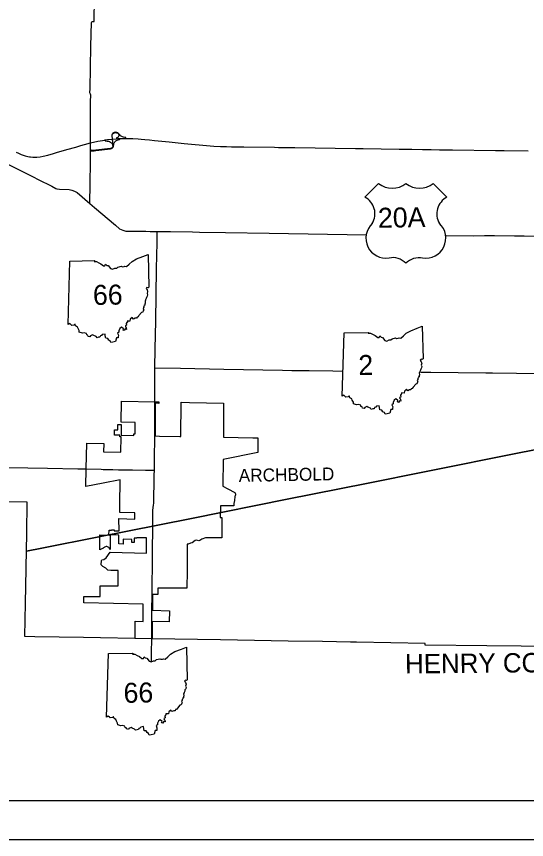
# Model space of a CAD drawing. Extents: x 0 to 849, y 0 to 440.
# Drawn here: x 135.7 to 267.5, y 0 to 212.6 of the extents above; entities that cross this region are included whole.
import ezdxf

# ---------------------------------------------------------------- set-up
doc = ezdxf.new("R2010")
doc.units = 0
for name, color, linetype in [('DV_X_Corp_Line', 7, 'Continuous'), ('GM_X_Adjacent_County_Text', 7, 'Continuous'), ('GM_X_Corporation_Text', 7, 'Continuous'), ('GM_X_County', 7, 'Continuous'), ('GM_X_Interchange_Ramps', 7, 'Continuous'), ('GM_X_Interstate_Route', 7, 'Continuous'), ('PV_P_Walk', 7, 'Continuous'), ('RD_X_RR_2', 7, 'Continuous'), ('SH_Border', 7, 'Continuous'), ('SH_Cut_Line', 7, 'Continuous')]:
    doc.layers.add(name, color=color, linetype=linetype)

msp = doc.modelspace()

# ---------------------------------------------------------------- linework, layer by layer
at = {"layer": 'DV_X_Corp_Line'}
msp.add_lwpolyline([(157.2, 77.1), (157.21, 78.66), (159.7, 78.59), (159.56, 78.74), (159.59, 79.89), (160.22, 79.89), (160.24, 79.97), (160.9, 79.99), (160.92, 79.74), (162.19, 79.7), (162.13, 82.88), (166.24, 82.79), (166.24, 84.37), (162.36, 84.48), (162.38, 86.49), (162.46, 92.87), (158.09, 92.04), (153.6, 91.15), (153.7, 95.78), (153.83, 102.38), (158.21, 102.29), (158.18, 100.17), (162.64, 100.09), (162.69, 103.98), (162.35, 103.99), (162.36, 104.42), (160.95, 104.44), (160.96, 105.85), (161.84, 105.85), (161.85, 107.21), (162.7, 107.19), (162.7, 104.41), (166.02, 104.34), (166.03, 104.79), (166.37, 104.79), (166.37, 107.72), (162.73, 107.8), (162.76, 113.26), (171.53, 113.08), (172.43, 113.07), (172.43, 112.65), (171.53, 112.67), (171.54, 112.32), (171.54, 110.86), (171.53, 108.11), (171.53, 105.38), (171.53, 104.24), (172.65, 104.21), (177.9, 104.11), (178.16, 104.11), (178.21, 112.95), (180.39, 112.91), (189.2, 112.74), (189.2, 103.9), (196.77, 103.79), (198.02, 103.78), (198.01, 99.99), (189.11, 98.19), (189.1, 98.04), (188.97, 91.57), (188.96, 91.24), (190.26, 90.57), (192.07, 89.64), (192.21, 89.46), (192.29, 89.22), (192.26, 89.03), (192.21, 88.8), (192.05, 88.6), (191.97, 87.56), (191.87, 86.79), (191.83, 86.19), (188.85, 86.23), (188.35, 86.23), (188.32, 83.16), (188.77, 83.16), (188.71, 77.9), (184.47, 77.9), (183.59, 77.54), (183.02, 77.21), (182.8, 77.17), (182.14, 77.33), (181.83, 77.22), (181.04, 76.66), (180.65, 76.55), (180.06, 76.29), (179.76, 76.27), (179.74, 69.37), (179.67, 64.92), (172.2, 64.92), (172.2, 63.28), (170.84, 63.28), (170.84, 61.36), (170.84, 59.21), (175.17, 59.11), (175.13, 56.21), (170.75, 56.3), (170.72, 51.85), (166.32, 51.95), (166.31, 53.93), (166.31, 56.38), (168.37, 56.34), (168.37, 60.78), (153.08, 61.15), (153.1, 62.8), (157.26, 62.74), (157.26, 65.51), (161.93, 65.51), (161.92, 69.45), (160.03, 69.46), (159.26, 69.58), (158.73, 70.08), (158, 70.53), (157.54, 70.96), (157.6, 72.11), (157.75, 72.25), (158.2, 72.34), (158.85, 72.76), (159.84, 74.24), (169.23, 74), (169.24, 77.89), (166.77, 77.95), (166.77, 77.85), (166.07, 77.86), (166.07, 76.69), (165.44, 76.69), (165.44, 77.49), (163.27, 77.57), (163.24, 76.31), (162.08, 76.37), (162.07, 78.63), (159.87, 78.69), (159.87, 78.59), (159.86, 74.92), (159.8, 74.96), (159.73, 75.05), (159.67, 75.23), (159.54, 75.41), (159.36, 75.54), (159.18, 75.64), (159, 75.67), (158.82, 75.66), (158.63, 75.61), (158.45, 75.53), (158.3, 75.43), (158.19, 75.35), (158.08, 75.2), (157.9, 75.13), (157.68, 75.07), (157.2, 74.86), (157.19, 75.64)], close=True, dxfattribs=at)
at = {"layer": 'GM_X_County'}
msp.add_lwpolyline([(274.97, 49.87), (257.21, 50.03), (241.23, 50.18), (241.23, 50.62), (223.56, 50.97), (222.01, 51), (214.7, 51.12), (205.85, 51.27), (192.81, 51.48), (188.37, 51.55), (170.6, 51.88), (152.98, 52.21), (140.37, 52.37), (137.82, 52.4), (137.99, 61.06), (138.17, 69.88), (138.17, 70.24), (138.3, 79.03), (138.42, 87.11), (120.76, 87.37)], dxfattribs=at)
at = {"layer": 'GM_X_Interchange_Ramps'}
for points in [[(154.8, 177.89), (154.93, 177.9), (155.75, 177.92), (156.18, 177.94), (159.97, 178.38), (160.2, 178.46), (160.39, 178.58), (160.53, 178.72), (160.63, 178.87), (160.72, 179.09), (160.76, 179.3), (160.79, 179.47), (160.86, 179.75), (160.91, 179.91), (161, 180.05), (161.11, 180.21), (161.2, 180.31), (161.33, 180.43), (161.47, 180.52), (161.65, 180.64), (161.83, 180.71), (161.96, 180.76), (162.1, 180.8), (162.26, 180.84), (162.39, 180.87), (162.37, 181.05)], [(163.94, 181.08), (163.93, 181.34), (163.63, 181.37), (163.31, 181.42), (163.09, 181.49), (162.9, 181.59), (162.69, 181.7), (162.56, 181.79), (162.44, 181.94), (162.28, 182.1), (162.15, 182.26), (161.98, 182.43), (161.83, 182.55), (161.6, 182.62), (161.43, 182.66), (161.26, 182.68), (161.11, 182.66), (160.91, 182.6), (160.72, 182.52), (160.59, 182.42), (160.47, 182.3), (160.4, 182.21), (160.33, 182.06), (160.31, 181.89), (160.42, 180.92), (160.58, 179.63), (160.45, 179.63)], [(160.79, 179.47), (160.68, 179.47), (160.51, 180.93), (160.4, 181.84), (160.42, 182.01), (160.49, 182.16), (160.56, 182.26), (160.68, 182.37), (160.82, 182.47), (161.01, 182.55), (161.21, 182.58), (161.39, 182.58), (161.55, 182.55), (161.69, 182.51), (161.88, 182.41), (162.02, 182.28), (162.14, 182.06), (162.16, 181.95), (162.12, 181.74), (162.05, 181.58), (161.94, 181.44), (161.81, 181.36), (161.68, 181.27), (161.47, 181.21), (161.5, 181)], [(158.56, 180.69), (158.57, 180.5), (159.13, 180.42), (159.4, 180.39), (159.7, 180.27), (159.96, 180.14), (160.13, 179.98), (160.29, 179.83), (160.45, 179.63), (160.51, 179.47), (160.58, 179.19), (160.55, 179.02), (160.46, 178.84), (160.32, 178.67), (160.18, 178.55), (159.98, 178.48), (156.15, 178.03), (155.73, 178.01), (154.93, 178.02), (154.8, 178.03)]]:
    msp.add_lwpolyline(points, dxfattribs=at)
at = {"layer": 'GM_X_Interstate_Route'}
msp.add_line((217.4, 121.04), (220.03, 121), dxfattribs=at)
for points in [[(154.66, 192.87), (154.66, 192.98), (154.68, 193.88), (154.9, 204.94), (155.08, 211.05), (155.13, 211.21), (155.24, 211.26), (155.71, 211.25), (155.78, 211.33), (155.76, 212.2), (155.8, 216.41), (155.83, 218.75), (155.85, 221.05)], [(154.83, 191.03), (154.84, 191.86), (154.84, 192.29), (154.8, 192.52), (154.66, 192.87)], [(154.82, 186.76), (154.82, 187.12), (154.82, 187.48), (154.83, 191.03)], [(154.8, 179.94), (154.8, 182.13), (154.82, 186.76)], [(157.87, 180.57), (158.38, 180.66), (158.56, 180.69), (159.18, 180.77), (160.42, 180.92), (160.51, 180.93), (161.5, 181), (161.96, 181.04), (162.37, 181.05), (163.28, 181.08), (163.94, 181.08), (165.77, 181.07), (167.12, 180.98), (167.88, 180.93), (168.87, 180.83), (170.02, 180.71), (171.37, 180.58), (172.27, 180.49)], [(135.62, 177.53), (136.17, 177.25), (136.57, 177.07), (136.9, 176.93), (137.38, 176.75), (137.93, 176.57), (138.59, 176.42), (138.99, 176.34), (139.32, 176.3), (139.9, 176.25), (140.45, 176.24), (140.95, 176.25), (141.75, 176.32), (142.6, 176.47), (143.77, 176.78), (145.2, 177.19), (145.97, 177.42), (148.68, 178.21), (150.96, 178.86), (152.33, 179.25), (153.21, 179.5), (154.8, 179.94), (156.66, 180.36), (157.87, 180.57)], [(154.64, 164.31), (154.7, 169.35), (154.79, 175.05), (154.8, 177.89), (154.8, 178.03), (154.8, 179.94)], [(172.27, 180.49), (175.09, 180.22), (179.02, 179.82), (180.92, 179.63), (183.79, 179.35), (186.7, 179.09), (188.41, 179), (189.91, 178.97), (191.22, 178.94), (194.39, 178.9), (202.32, 178.79), (203.33, 178.77), (207.55, 178.72), (223.28, 178.5), (224.64, 178.47), (225.21, 178.47), (234.57, 178.34), (237.8, 178.29), (240.55, 178.25), (242.85, 178.22), (245.01, 178.17), (246.12, 178.16), (248.34, 178.13), (259.43, 177.97), (261.71, 177.94), (267.92, 177.85)], [(89.71, 175.79), (113.47, 175.61), (130.69, 175.58), (131.12, 175.5), (131.5, 175.42), (137.58, 172.34), (139.83, 171.25), (141.43, 170.41), (144.59, 168.83), (144.77, 168.74), (145.86, 168.18), (146.13, 168.08), (146.75, 167.98), (149.29, 167.86), (150.01, 167.74), (150.65, 167.5), (151.32, 167.09), (154.64, 164.31), (155.86, 163.24), (161.21, 158.65), (162.29, 157.78), (163.12, 157.38), (163.95, 157.14), (169.06, 157.1)], [(169.06, 157.1), (170.22, 157.09)], [(170.22, 157.09), (172.03, 157.08)], [(172, 154.84), (172.01, 155.79), (172.03, 157.08)], [(172.03, 157.08), (174.43, 157.04), (174.6, 157.04)], [(174.6, 157.04), (175.45, 157.02), (181.18, 156.93)], [(181.18, 156.93), (182.96, 156.9), (189.68, 156.81), (200.94, 156.66), (226.14, 156.17)], [(246.72, 156), (253.77, 155.97), (256.58, 155.99), (259.15, 156), (264.38, 155.97), (266.86, 155.96), (270.84, 155.82), (274.09, 155.71), (276.76, 155.61), (280.09, 155.59), (286.89, 155.53), (294.34, 155.48), (296.6, 155.47), (305.33, 155.42), (310.78, 155.43), (310.81, 155.43)], [(171.93, 150.82), (171.98, 154.08), (172, 154.84)], [(171.64, 133.85), (171.87, 147.38), (171.93, 150.82)], [(171.44, 121.8), (171.51, 126.75), (171.64, 133.85)], [(171.45, 116.21), (171.43, 120.06), (171.44, 121.8)], [(171.44, 121.8), (178.08, 121.71), (189.25, 121.52), (204.37, 121.21)], [(204.37, 121.21), (206.81, 121.16), (208.96, 121.13), (208.96, 121.13)], [(208.96, 121.13), (211.27, 121.11), (217.4, 121.04), (217.4, 121.04)], [(240.16, 120.71), (242.74, 120.69), (242.74, 120.69)], [(242.74, 120.69), (249.83, 120.66), (256.91, 120.58), (258.65, 120.56), (264.84, 120.5), (276.4, 120.37)], [(171.45, 112.89), (171.45, 114.08), (171.45, 116.21)], [(171.45, 112.72), (171.45, 112.89), (171.45, 112.89)], [(171.45, 112.37), (171.45, 112.71), (171.45, 112.72)], [(171.41, 104.16), (171.42, 105.27), (171.43, 105.71), (171.44, 108.03), (171.44, 110.76), (171.45, 112.02)], [(171.45, 112.02), (171.45, 112.37), (171.45, 112.37)], [(171.35, 97.93), (171.36, 98.98), (171.37, 99.66), (171.37, 99.87), (171.4, 102.5), (171.41, 104.16)], [(171.31, 95.39), (171.32, 95.73), (171.33, 96.77), (171.34, 97.86), (171.35, 97.93)], [(98.03, 96.21), (105.45, 96.33), (108.5, 96.35), (111.2, 96.26), (112.11, 96.24), (117.86, 96.23), (120.9, 96.2), (124.77, 96.16), (128.59, 96.13), (129.07, 96.12), (130.38, 96.11), (131.54, 96.1), (138.56, 96.03), (143.66, 95.94), (151.56, 95.77), (153.67, 95.72)], [(153.67, 95.72), (157.55, 95.62), (158.03, 95.61), (158.04, 95.61)], [(158.04, 95.61), (160.35, 95.55), (160.58, 95.55), (162.01, 95.52), (162.83, 95.51), (163.55, 95.49), (164.67, 95.47), (164.68, 95.47)], [(164.68, 95.47), (164.7, 95.47), (165.68, 95.45), (169.02, 95.39), (169.07, 95.39), (169.74, 95.39)], [(169.74, 95.39), (170.2, 95.39), (171.31, 95.39)], [(171.15, 88.15), (171.15, 88.15), (171.16, 88.69), (171.18, 89.76), (171.21, 90.82), (171.24, 92.26), (171.28, 93.85), (171.28, 94.01), (171.28, 94.01)], [(171.28, 94.01), (171.28, 94.14), (171.31, 95.39)], [(171.12, 86.77), (171.12, 86.77), (171.13, 87.62), (171.15, 88.15)], [(170.85, 76.81), (170.86, 78.24), (170.88, 80.03), (170.89, 80.91), (170.91, 82.56), (170.93, 84.97), (171.11, 86.42), (171.11, 86.43), (171.12, 86.77)], [(170.82, 74.31), (170.85, 76.81)], [(170.71, 63.15), (170.73, 65.42), (170.75, 67.25), (170.78, 69.49), (170.8, 72.19), (170.82, 74.31), (170.82, 74.31)], [(170.67, 59.28), (170.71, 63.15), (170.71, 63.15)], [(170.64, 56.28), (170.67, 59.28), (170.67, 59.28)], [(170.62, 53.99), (170.64, 56.28), (170.64, 56.28)], [(170.54, 46.04), (170.62, 53.99)]]:
    msp.add_lwpolyline(points, dxfattribs=at)
at = {"layer": 'PV_P_Walk'}
for p, q in [((229.24, 169.45), (225.7, 165.9)), ((246.88, 165.9), (243.33, 169.45)), ((148.99, 133.04), (149.45, 149.42)), ((219.85, 114.52), (220.31, 130.89)), ((158.94, 31.64), (159.4, 48.01))]:
    msp.add_line(p, q, dxfattribs=at)
for points in [[(149.45, 149.42), (155.8, 149.52), (155.7, 149.32), (156.3, 149.28), (156.94, 148.93), (157.48, 148.71), (158.13, 148.19), (158.53, 148.2), (158.69, 148.62), (159, 148.3), (159.35, 148.24), (159.97, 147.45), (160.49, 147.28), (161.1, 147.55), (161.56, 147.6), (161.89, 147.86), (162.76, 148.09), (163, 147.95), (163.47, 147.98), (163.7, 148.08), (164.1, 147.99), (164.81, 148.59), (165.54, 149.29), (166.66, 149.95), (168.34, 150.58), (169.66, 151.14), (169.85, 142.64)], [(169.85, 142.64), (169.66, 142.52), (169.35, 142.58), (169.15, 142.34), (169.4, 141.94), (169.52, 141.52), (169.42, 141.06), (169.52, 140.68), (169.45, 140.36), (169.26, 140.04), (169.19, 139.74), (169.03, 139.42), (169.04, 139.24), (168.89, 139.1), (168.92, 138.57), (168.84, 138.27), (168.86, 138.02), (168.61, 137.95), (168.67, 137.74), (168.51, 137.58), (168.54, 137.3), (168.36, 137.12), (168.54, 136.77), (168.4, 136.65), (168.28, 136.22), (167.96, 136.13), (167.31, 135.34), (167.08, 135.04), (166.83, 134.96), (166.69, 134.66), (166.37, 134.65), (165.89, 134.44), (165.59, 134.81), (165.04, 134.37), (164.98, 133.86), (164.3, 133.87), (164.33, 133.61), (164.17, 133.54), (164.03, 133.28), (164.12, 132.82), (163.8, 132.7), (163.83, 132.44), (164.04, 132.27), (164.13, 131.76), (163.79, 131.87), (163.51, 131.44), (163.23, 131.54), (163.32, 131.9), (162.83, 132.34), (162.38, 131.99), (162.14, 131.43), (162.14, 131.05), (161.79, 130.82), (162.01, 130.29), (161.97, 129.92), (161.98, 129.58), (161.55, 129.59), (161.29, 128.65)], [(161.29, 128.65), (160.55, 128.47), (160.04, 128.36), (159.86, 128.79), (159.49, 129.01), (159.25, 129.44), (158.72, 129.5), (158.6, 130.09), (158.54, 130.57), (157.81, 130.45), (157.62, 130.16), (157.36, 130.08), (157.21, 129.79), (156.86, 129.76), (156.49, 129.62), (156.24, 129.91), (155.63, 130.2), (155.35, 130.35), (154.77, 130.12), (154.65, 129.84), (154.19, 129.97), (154.08, 130.27), (153.81, 130.37), (153.74, 130.69), (153.15, 130.87), (152.7, 130.8), (151.89, 131.06), (151.84, 131.49), (151.57, 132.01), (151.43, 132.37), (150.92, 132.65), (150.82, 133.08), (150.66, 133.07), (150.51, 132.89), (149.95, 132.81), (149.72, 132.99), (149.41, 133.29), (148.99, 133.04)], [(220.31, 130.89), (226.66, 131), (226.57, 130.8), (227.16, 130.76), (227.8, 130.41), (228.34, 130.19), (229, 129.67), (229.39, 129.68), (229.56, 130.1), (229.86, 129.77), (230.22, 129.71), (230.84, 128.93), (231.35, 128.76), (231.96, 129.03), (232.42, 129.07), (232.75, 129.34), (233.63, 129.57), (233.87, 129.43), (234.33, 129.46), (234.56, 129.56), (234.97, 129.47), (235.67, 130.06), (236.4, 130.77), (237.53, 131.43), (239.2, 132.05), (240.53, 132.62), (240.72, 124.12)], [(240.72, 124.12), (240.52, 124), (240.22, 124.06), (240.01, 123.82), (240.27, 123.42), (240.39, 123), (240.28, 122.54), (240.38, 122.16), (240.31, 121.84), (240.12, 121.52), (240.06, 121.21), (239.89, 120.89), (239.91, 120.72), (239.75, 120.57), (239.78, 120.04), (239.7, 119.75), (239.73, 119.49), (239.48, 119.43), (239.53, 119.22), (239.37, 119.06), (239.41, 118.78), (239.23, 118.6), (239.4, 118.24), (239.26, 118.13), (239.14, 117.7), (238.82, 117.61), (238.18, 116.81), (237.95, 116.52), (237.69, 116.44), (237.55, 116.13), (237.24, 116.13), (236.76, 115.92), (236.45, 116.29), (235.91, 115.84), (235.85, 115.33), (235.16, 115.35), (235.19, 115.09), (235.04, 115.02), (234.9, 114.76), (234.98, 114.3), (234.66, 114.18), (234.7, 113.91), (234.9, 113.75), (234.99, 113.24), (234.65, 113.34), (234.38, 112.91), (234.09, 113.02), (234.18, 113.38), (233.7, 113.82), (233.24, 113.47), (233, 112.91), (233, 112.53), (232.66, 112.3), (232.88, 111.77), (232.84, 111.4), (232.84, 111.05), (232.42, 111.07), (232.16, 110.13)], [(232.16, 110.13), (231.42, 109.95), (230.9, 109.84), (230.72, 110.27), (230.35, 110.49), (230.11, 110.92), (229.59, 110.98), (229.46, 111.57), (229.4, 112.05), (228.68, 111.93), (228.48, 111.64), (228.22, 111.56), (228.08, 111.26), (227.73, 111.24), (227.35, 111.1), (227.11, 111.39), (226.49, 111.68), (226.22, 111.83), (225.64, 111.6), (225.52, 111.32), (225.06, 111.44), (224.95, 111.75), (224.67, 111.84), (224.61, 112.17), (224.01, 112.34), (223.56, 112.27), (222.76, 112.54), (222.71, 112.97), (222.44, 113.49), (222.29, 113.85), (221.79, 114.13), (221.68, 114.56), (221.52, 114.55), (221.37, 114.37), (220.81, 114.29), (220.59, 114.47), (220.27, 114.77), (219.85, 114.52)], [(159.4, 48.01), (165.75, 48.12), (165.65, 47.92), (166.25, 47.88), (166.89, 47.53), (167.43, 47.31), (168.09, 46.79), (168.48, 46.79), (168.65, 47.22), (168.95, 46.89), (169.31, 46.83), (169.93, 46.05), (170.44, 45.88), (171.05, 46.15), (171.51, 46.19), (171.84, 46.46), (172.71, 46.68), (172.96, 46.55), (173.42, 46.57), (173.65, 46.67), (174.05, 46.58), (174.76, 47.18), (175.49, 47.88), (176.61, 48.54), (178.29, 49.17), (179.62, 49.73), (179.81, 41.24)], [(179.81, 41.24), (179.61, 41.12), (179.31, 41.17), (179.1, 40.93), (179.36, 40.54), (179.47, 40.12), (179.37, 39.65), (179.47, 39.27), (179.4, 38.95), (179.21, 38.63), (179.14, 38.33), (178.98, 38.01), (179, 37.83), (178.84, 37.69), (178.87, 37.16), (178.79, 36.87), (178.82, 36.61), (178.57, 36.54), (178.62, 36.33), (178.46, 36.17), (178.5, 35.89), (178.32, 35.72), (178.49, 35.36), (178.35, 35.25), (178.23, 34.81), (177.91, 34.72), (177.26, 33.93), (177.04, 33.63), (176.78, 33.56), (176.64, 33.25), (176.32, 33.25), (175.85, 33.03), (175.54, 33.4), (175, 32.96), (174.94, 32.45), (174.25, 32.47), (174.28, 32.21), (174.13, 32.13), (173.99, 31.87), (174.07, 31.41), (173.75, 31.3), (173.79, 31.03), (173.99, 30.87), (174.08, 30.36), (173.74, 30.46), (173.46, 30.03), (173.18, 30.13), (173.27, 30.5), (172.79, 30.93), (172.33, 30.58), (172.09, 30.02), (172.09, 29.65), (171.75, 29.42), (171.97, 28.89), (171.93, 28.52), (171.93, 28.17), (171.51, 28.18), (171.25, 27.24)], [(171.25, 27.24), (170.51, 27.06), (169.99, 26.96), (169.81, 27.38), (169.44, 27.61), (169.2, 28.04), (168.67, 28.1), (168.55, 28.69), (168.49, 29.17), (167.77, 29.05), (167.57, 28.75), (167.31, 28.68), (167.16, 28.38), (166.81, 28.36), (166.44, 28.22), (166.19, 28.51), (165.58, 28.8), (165.3, 28.95), (164.73, 28.71), (164.6, 28.44), (164.14, 28.56), (164.04, 28.87), (163.76, 28.96), (163.7, 29.29), (163.1, 29.46), (162.65, 29.39), (161.85, 29.65), (161.8, 30.08), (161.52, 30.6), (161.38, 30.97), (160.87, 31.24), (160.77, 31.68), (160.61, 31.66), (160.46, 31.49), (159.9, 31.41), (159.67, 31.58), (159.36, 31.89), (158.94, 31.64)]]:
    msp.add_lwpolyline(points, dxfattribs=at)
for centre, radius, start, end in [((232.76, 173.93), 5.7, 231.813, 308.187), ((239.81, 173.93), 5.7, 231.813, 308.187), ((223.48, 161.62), 4.82, 329.1175, 62.6108), ((249.1, 161.62), 4.82, 117.3892, 210.8825), ((231.16, 155.35), 5.2, 133.0046, 278.7282), ((241.41, 155.35), 5.2, 261.2718, 46.9954), ((232.91, 145.65), 4.65, 43.4177, 101.8742), ((239.76, 145.34), 4.94, 79.9613, 134.7468)]:
    msp.add_arc(centre, radius, start, end, dxfattribs=at)
at = {"layer": 'RD_X_RR_2'}
for points in [[(340.35, 114.38), (323.72, 111.19), (296.49, 105.88), (265.55, 99.86), (241.52, 95.04), (226.11, 92), (226.13, 92.01)], [(226.11, 92), (241.52, 95.04), (265.55, 99.86), (296.49, 105.88), (323.72, 111.19), (340.38, 114.29)], [(226.11, 92), (205.62, 87.92), (180.86, 82.88), (164.33, 79.66), (156.94, 78.18), (142.22, 75.25), (138.22, 74.45), (138.22, 74.54)], [(138.22, 74.54), (138.22, 74.45), (142.22, 75.25), (156.94, 78.18), (164.33, 79.66), (180.86, 82.88), (205.62, 87.92), (226.11, 92)]]:
    msp.add_lwpolyline(points, dxfattribs=at)
at = {"layer": 'SH_Border'}
msp.add_lwpolyline([(30, 430), (670, 430), (670, 10), (30, 10)], close=True, dxfattribs=at)
at = {"layer": 'SH_Cut_Line'}
msp.add_lwpolyline([(0, 0), (680, 0), (680, 440), (0, 440)], close=True, dxfattribs=at)

# ---------------------------------------------------------------- texts
at = {"layer": 'GM_X_Adjacent_County_Text'}
msp.add_text('HENRY COUNTY', height=5.0058, rotation=0.5197, dxfattribs=at).set_placement((236.08, 42.88))
at = {"layer": 'GM_X_Corporation_Text'}
msp.add_text('ARCHBOLD', height=3.325, rotation=1.0142, dxfattribs=at).set_placement((193.12, 92.37))
at = {"layer": 'PV_P_Walk'}
for s, p in [('20A', (229.1, 157.99)), ('66', (155.46, 138.06)), (' 2 ', (222.13, 119.92)), ('66', (163.37, 35.29))]:
    msp.add_text(s, height=5.162, rotation=1.0142, dxfattribs=at).set_placement(p)

doc.saveas('drawing.dxf')
